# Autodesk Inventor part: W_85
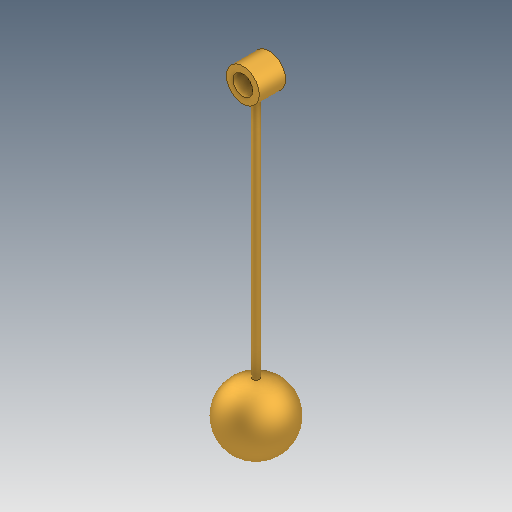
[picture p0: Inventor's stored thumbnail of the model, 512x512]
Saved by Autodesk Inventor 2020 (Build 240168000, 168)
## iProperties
Created: 2021-01
Part Number: W_85
Material: Mosiądz, miękki żółty
Document SubType Name: Modeling
Designer: Home
Mass: 40.8568 g
Surface Area: 22.1839 cm^2
Volume: 4.82371 cm^3
Density: 8.47 g/cm^3
Appearance: Mosiądz — satynowy
Author: Home
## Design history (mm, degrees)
sketch "Szkic1"
  geometry: L1 (0, 10)-(0, -10); A1 r 10 centre (0, 0) between (0, 10) and (0, -10); 1 further point
  constraints: 2 end point, 2 point on circle, 1 centre point, 1 coincident, 1 vertical, 1 vertical alignment
  dimensions: "d0" = 20 diameter of A1
revolve "Obrót1" sketch "Szkic1" stored, may be unused: angle "d1" = 90 deg
sketch "Szkic2"
  geometry: L1 (-1, 0)-(1, 0); L2 (1, 0)-(1, 85); L3 (1, 85)-(-1, 85); L4 (-1, 85)-(-1, 0); L5 (0, 85)-(0, 0); 1 further point
  constraints: 10 end point, 3 parallel, 2 midpoint, 1 coincident, 1 horizontal, 1 perpendicular, 1 vertical alignment
  dimensions: "d2" = 2 distance between parallel lines of L4 L2; "d3" = 85 distance of L1.end L2.end
revolve "Obrót2" sketch "Szkic2" stored, may be unused: angle "d4" = 90 deg
sketch "Szkic3"
  geometry: L1 (1, 85)-(-1, 85) reference; C1 r 5 at (0, 89); C2 r 3 at (0, 89); 1 further point
  constraints: 2 centre point, 1 coincident
  dimensions: "d5" = 10 diameter of C1; "d6" = 6 diameter of C2; "d7" = 4 distance from line of L1 C2.centre
extrude "Wyciągnięcie proste1" join sketch "Szkic3" stored distance "d8" = 8; taper "d9" = 0 deg
node "Bryła1"
